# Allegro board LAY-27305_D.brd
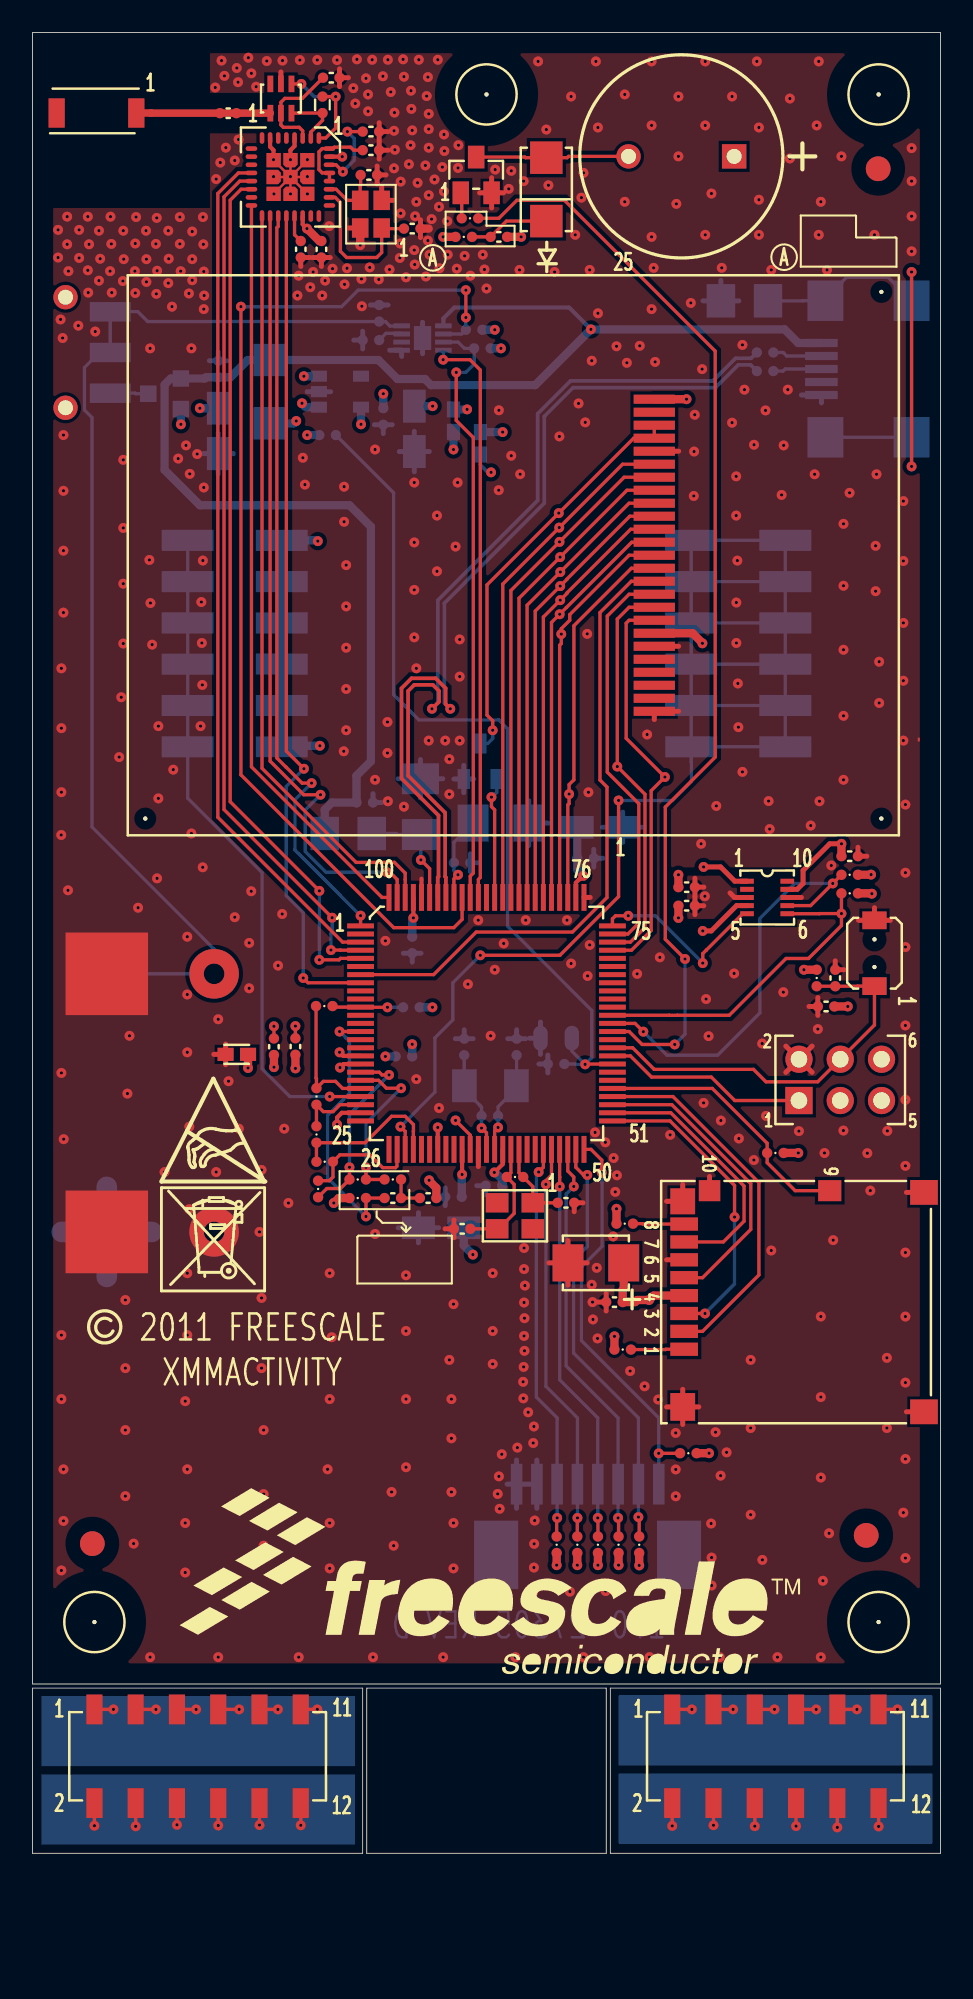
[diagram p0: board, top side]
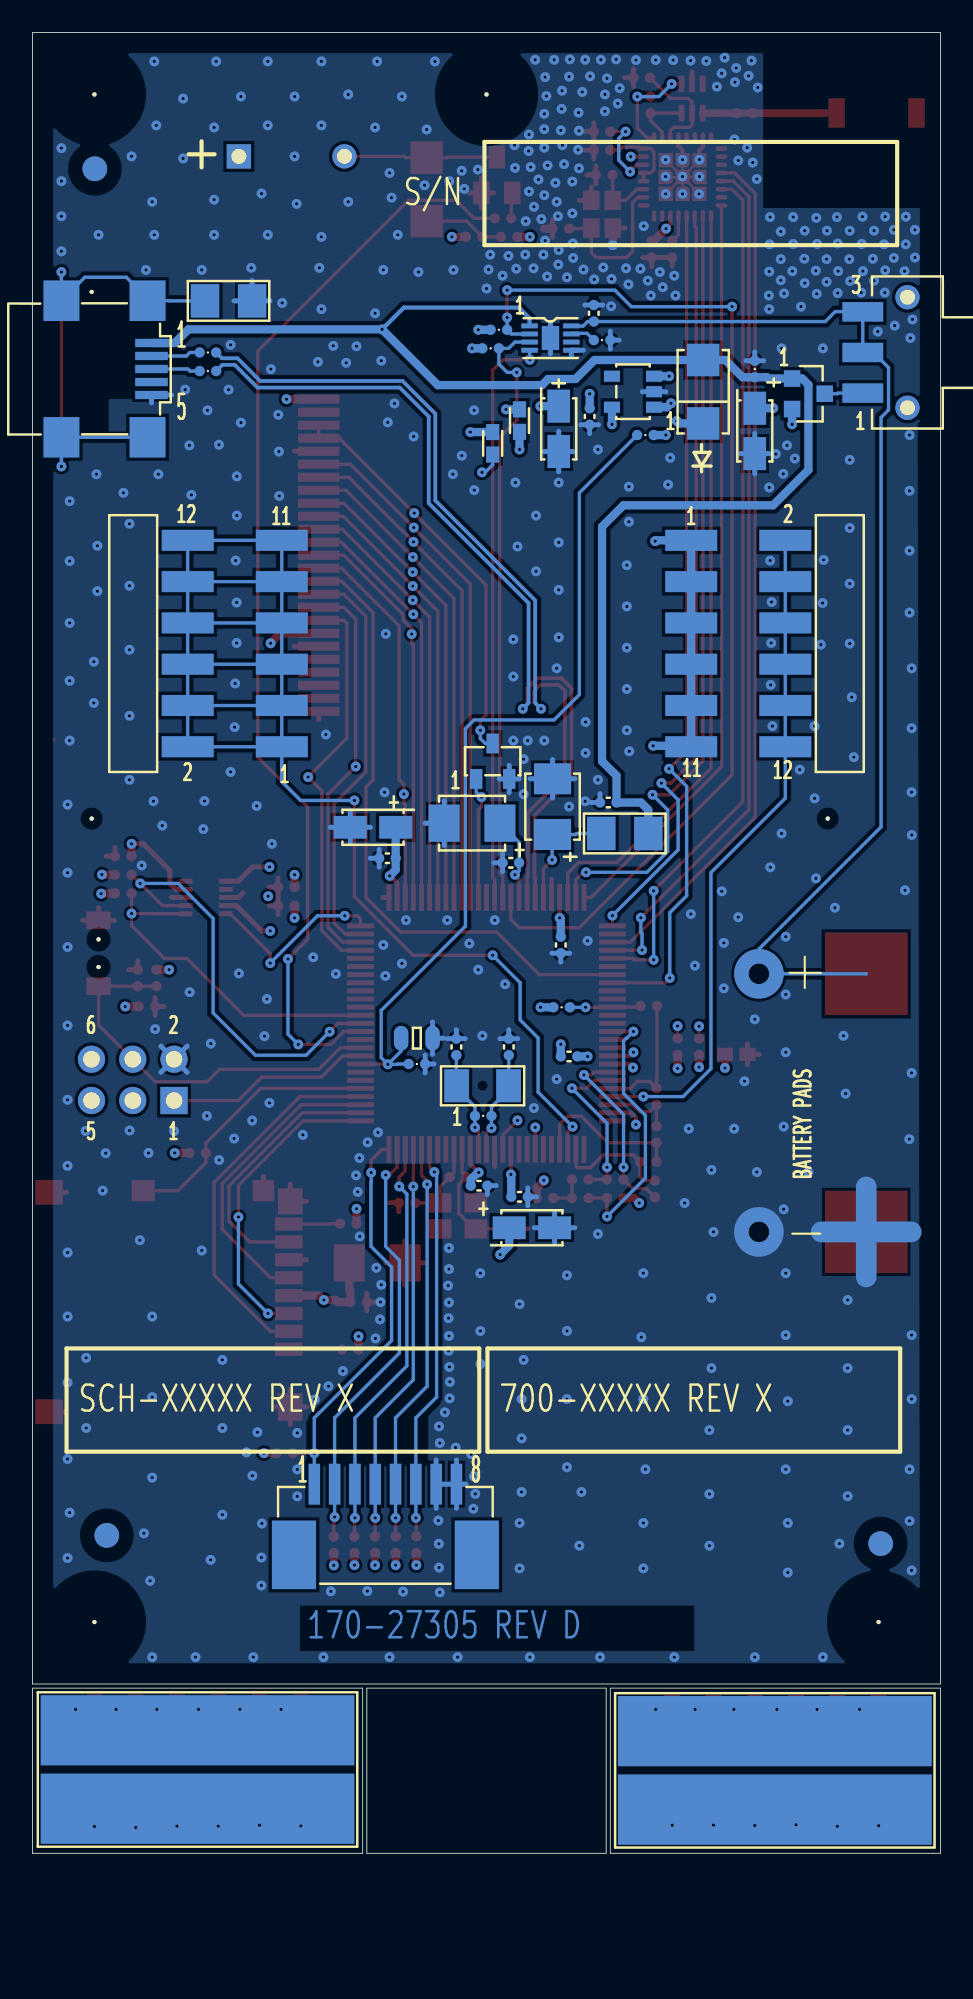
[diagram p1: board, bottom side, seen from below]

Outline 55.88 x 112.01 mm; copper layers: TOP, L2_GND_1, L3_PWR_1, L4_PWR_2, L5_GND_2, BOTTOM. Coordinates in mm from the lower left corner of the outline.
Outline path: 0,112.01 0,10.41 55.88,10.41 55.88,112.01 0,112.01 ; 0,10.16 20.32,10.16 20.32,0 0,0 0,10.16 ; 20.57,10.16 35.31,10.16 35.31,0 20.57,0 20.57,10.16 ; 35.56,10.16 55.88,10.16 55.88,0 35.56,0 35.56,10.16

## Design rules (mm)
net group DP1: nets USBDM USBDP
nets with their own width: min track width 0.305; nets VDDA

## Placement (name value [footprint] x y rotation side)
C1  0.47UF  [CC0402_25]  26.44 60.93 0 bottom
C2  4.7UF  [CC3528-21]  28.83 63.37 0 bottom
C3  4.7UF  [CC3528-21]  23.88 64.39 90 bottom
C4  1.0UF  [CC0402_25]  20.45 64.64 0 bottom
C5  2.2UF  [CC0402_25]  21.34 94.74 90 bottom
C6  10UF  [CC3216]  11.43 87.5 270 bottom
C7  0.1uF  [CC0402_25]  21.59 88.39 270 bottom
C8  10UF  [CC3216]  23.5 87.63 270 bottom
C9  0.1uF  [CC0402_25]  35.81 33.91 180 top
C10  4.7UF  [CC3528-21]  34.67 36.32 180 top
C11  0.1UF  [CC0402_25]  14.86 49.62 270 top
C12  0.01UF  [CC0402_25]  16.18 49.63 270 top
C13  10UF  [CC3216]  34.92 63.12 0 bottom
C14  0.1UF  [CC0402_25]  23.37 55.88 270 bottom
C15  0.1UF  [CC0402_25]  34.04 61.21 0 bottom
C16  0.1UF  [CC0402_25]  28.4 41.07 180 bottom
C17  10UF  [CC3216]  25.15 38.48 180 bottom
C20  0.1UF  [CC0402_25]  48.84 52.1 180 top
C21  0.1UF  [CC0402_25]  40.26 58.29 180 top
C22  0.1UF  [CC0402_25]  50.29 61.34 0 top
C23  0.1UF  [CC0402_25]  25.91 40.39 180 bottom
C24  0.1UF  [CC0402_25]  22.86 49.02 0 bottom
C25  0.1UF  [CC0402_25]  49.4 53.85 270 top
C28  12PF  [CC0402_25]  26.44 38.42 0 top
C29  12PF  [CC0402_25]  32.83 40.02 180 top
C30  0.1uF  [CC0402_25]  20.83 105.92 0 top
C31  0.1uF  [CC0402_25]  16.51 98.68 270 top
C32  0.1uF  [CC0402_25]  20.83 104.78 0 top
C33  1UF  [CC0402_25]  17.78 98.68 270 top
C34  10PF  [CC0402_25]  18.39 109.23 0 top
C35  10PF  [CC0402_25]  12.04 107.05 180 top
C36  6.8PF  [CC0402_25]  23.37 99.95 0 top
C37  6.8PF  [CC0402_25]  20.7 103.25 0 top
C38  0.1uF  [CC0402_25]  24.35 40.31 0 top
C39  0.1uF  [CC0402_25]  22.17 40.31 180 top
C40  0.01UF  [CC0402_25]  40.26 59.44 180 top
C41  0.01UF  [CC0402_25]  28.7 99.44 180 top
C42  18PF  [CC0402_25]  26.57 49.61 270 bottom
C43  18PF  [CC0402_25]  29.79 49.61 270 bottom
C45  0.1uF  [CC0805_OV]  32.23 50.14 180 bottom
CN1  Conn MicroSD  [CON_SDCARD_8F_SM_RA]  46.99 33.91 270 top
D1  FM4001  [DO214AC_AK]  14.61 89.92 90 bottom
D2  FM4001  [DO214AC_AK]  31.62 102.36 90 top
DS1  NHD-1.8-128160ZF-CTXL#  [LCDMODULE_25P_0P8_34X47_SMT]  29.59 79.86 90 top
E1  ANTENNA_2400MHZ  [ANTENNA-2450]  3.94 107.06 180 top
E3  ELECTRODE  [ELECTRODE2_REC_760X360]  10.2 5.1 180 bottom
E4  ELECTRODE  [ELECTRODE2_REC_760X360]  45.73 5.15 180 bottom
J1  USB-MiniB  [CON5_MUSB_B_SKT_RA_SM]  50.8 91.31 180 bottom
J3  08FFS-SP-TF  [CON_FFS_8F_50_SM_RA]  34.16 19.56 180 bottom
J8  CON SKT 12  [CON2X6_100_SM]  45.72 5.97 90 top
J9  CON PLUG 12  [CON2X6_100_RA_SM]  12.45 74.42 180 bottom
J10  CON PLUG 12  [CON2X6_100_RA_SM]  43.43 74.42 0 bottom
J11  CON SKT 12  [CON2X6_100_SM]  10.16 5.97 90 top
J12  HDR_2X3  [HDR203]  47.17 46.31 90 top
L1  26OHM  [IND_1206A]  43.81 95.5 180 bottom
L2  26OHM  [IND_1206A]  19.43 62.74 0 bottom
L3  100MHZ  [IND_0603]  12.57 49.15 180 top
L4  100MHZ  [IND_0603]  27.56 86.74 90 bottom
L5  100MHZ  [IND_0603]  25.91 88.14 90 bottom
L6  4.7nH  [IND_0402]  17.85 107.56 90 top
LS1  CSQG703BP  [BUZZER_6P5_12X3P8_TH]  43.18 104.39 180 top
NOREF  -  []  5.08 15.49 0 top
NOREF#2  -  []  35.56 0 0 top
NOREF#3  -  []  52.11 4.45 0 top
NOREF#4  -  []  3.17 13.59 0 top
NOREF#5  -  [unnamed#2]  52.07 108.2 0 top
NOREF#6  -  []  0 0 0 top
NOREF#7  -  []  55.88 10.41 90 top
NOREF#8  -  [unnamed#2]  51.31 19.56 0 top
NOREF#9  -  []  7.96 41.33 0 top
NOREF#10  -  []  222.76 -43.18 90 top
NOREF#11  -  []  372.36 -49.02 90 top
NOREF#12  -  []  201.42 112.9 0 top
NOREF#13  -  [unnamed#2]  3.68 19.05 0 top
NOREF#14  -  []  9.05 14.05 0 top
NOREF#15  -  []  243.08 -61.47 90 top
NOREF#16  -  []  -309.88 -248.03 0 top
NOREF#17  -  [unnamed#2]  52.04 103.63 0 top
NOREF#18  -  []  -285.75 277.75 0 top
NOREF#19  -  [unnamed#2]  52.07 14.22 0 top
NOREF#20  -  []  55.88 0 90 top
NOREF#21  -  []  0 112.01 0 top
NOREF#22  -  []  -23.98 -32.45 0 top
NOREF#23  -  [unnamed#2]  27.94 108.2 0 top
NOREF#24  -  []  4.57 32.51 0 top
NOREF#25  -  []  0 0 90 top
NOREF#26  -  [unnamed#2]  3.81 14.22 0 top
NOREF#27  -  []  5.08 15.49 0 top
NOREF#28  -  []  169.82 114.71 0 top
NOREF#29  -  []  55.88 10.16 0 top
NOREF#30  -  []  35.31 -0.25 0 top
NOREF#31  -  []  7.93 34.59 0 top
NOREF#32  -  []  3.56 4.57 0 top
NOREF#33  -  []  23.55 19.19 180 bottom
NOREF#34  -  []  53.59 29.59 180 bottom
NOREF#35  -  []  28.07 98.93 180 bottom
NOREF#36  -  [unnamed#2]  51.31 19.56 180 bottom
NOREF#37  -  [unnamed#2]  52.04 103.63 180 bottom
NOREF#38  -  [unnamed#2]  3.68 19.05 180 bottom
NOREF#39  -  []  27.69 29.59 180 bottom
Q1  ZXM61P02F  [SOT23-40X40]  8.13 89.79 270 bottom
Q3  MMBT5179  [SOT-23]  27.3 103.25 0 top
Q4  BSH103  [SOT23]  27.56 67.18 180 bottom
R3  33  [RC0402_25]  45.09 92.33 180 bottom
R4  33  [RC0402_25]  45.09 91.19 180 bottom
R5  4.7K  [RC0402_25]  27.18 93.73 180 bottom
R6  4.7K  [RC0402_25]  27.69 92.58 180 bottom
R8  1K  [RC0402_25]  11.43 91.31 90 bottom
R9  4.7K  [RC0402_25]  50.29 60.2 180 top
R10  10K  [RC0402_25]  36.32 30.99 0 top
R11  10K  [RC0402_25]  36.45 38.73 0 top
R12  10K  [RC0402_25]  45.72 43.08 180 top
R13  4.7K  [RC0402_25]  50.29 59.05 180 top
R15  1M  [RC0402_25]  29.69 41.61 0 top
R17  4.7K  [RC0402_25]  48.26 53.85 270 top
R18  1M  [RC0402_25]  32.22 48.56 180 bottom
R19  1M  [RC0402_25]  18.16 87.25 0 bottom
R20  1M  [RC0402_25]  17.48 44.22 90 top
R21  10K  [RC0402_25]  17.98 42.55 0 top
R22  10K  [RC0402_25]  17.48 46.56 90 top
R27  100K  [RC0402_25]  20.02 41.45 0 top
R28  100K  [RC0402_25]  23.32 52.04 0 bottom
R34  3.3K  [RC0402_25]  17.58 40.87 270 top
R35  3.3K  [RC0402_25]  17.96 52.12 0 top
R36  33K  [RC0402_25]  22.17 41.45 0 top
R38  1M  [RC0402_25]  20.02 40.31 180 top
R39  10K  [RC0402_25]  20.83 93.09 180 bottom
R40  470  [RC0402_25]  26.92 100.58 180 top
R41  0  [RC0402_25]  26.54 99.44 0 top
R42  1M  [RC0402_25]  28.14 45.36 0 bottom
R43  1M  [RC0402_25]  34.8 18.98 90 top
R44  1M  [RC0402_25]  33.53 18.98 90 top
R45  1M  [RC0402_25]  32.26 18.98 90 top
R46  1M  [RC0402_25]  36.07 18.98 90 top
R47  1M  [RC0402_25]  37.34 18.98 90 top
R48  1M  [RC0402_25]  40.36 24.61 180 top
SW1  JS102011SAQN  [SW3_SPDT_RA_SM]  2.03 92.33 0 bottom
SW2  SW2_STM151XX  [SW2_4X3MM_SM]  51.82 55.37 90 top
TP29  -  [TPAD_030]  4.57 38.23 0 top
TP30  -  [TPAD_030]  4.57 54.1 0 top
U1  MCF51MM256  [LQFP100_0P5_14X14]  27.94 51.05 0 top
U2  MC34673AEP  [DFN_8_0P5_2X3]  24 93.22 180 bottom
U3  LP2981IM5X3.3/NOPB  [SOT-23-5]  18.92 89.92 90 bottom
U5  MC13202FC  [QFN32_MC1320X]  15.88 103.12 270 top
U6  MMA7660FC  [DFN_10_0P5_3X3A]  45.21 58.8 0 top
Y1  16 MHz  [XTLOSC4_2P6X2P1MM_SM]  20.83 100.84 90 top
Y3  16MHZ  [XTLOSC4_3P2X2P5MM_SM]  29.69 39.22 180 top
Y4  32.768KHz  [XTL2_4P2X1P6]  28.18 47.22 180 bottom
Z1  50/200 OHMS  [XFMR6_0P65_2X1]  15.29 107.95 0 top

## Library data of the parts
C1 C4 C5 C7 C9 C11 C12 C14-C16 C20-C25 C28-C43 C45 = CAP_NP
C2 C3 C6 C8 C10 C13 C17 = CAP_POL
CN1 = CONN_MICRO_SD_CARD_REVERSED
D1 D2 = 3A_20V_SS32
DS1 = LCDMODULE_NHD_25P
E1 = ANTENNA_2P4GHZ
E3 E4 = ELECTRODE_B
J1 = USB_MINI_B_SKT
J3 = HDR_1X8_M
J8-J11 = CONN_HDR_6X2
J12 = CONN_HDR_3X2
L1 L2 = BEAD
L3-L5 = IND
L6 = INDUCTOR
LS1 = SPEAKER
Q1 = MOSFET_P
Q3 = NPN
Q4 = MOSFET_N
R3-R6 R8-R13 R15 R17-R22 R27 R28 R34-R36 R38-R48 = RES
SW1 = SW3_SPDT_SLIDE
SW2 = SW2_STM151XX
TP29 TP30 = TestLoop
U1 = MCF51MM256
U2 = MC34673AEP
U3 = LP2980_M5
U5 = MC13202FC
U6 = MMA7660FC
Y1 Y3 = XTAL_0
Y4 = XTAL
Z1 = LDB_21

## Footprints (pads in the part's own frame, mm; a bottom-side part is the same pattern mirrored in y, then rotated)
ANTENNA-2450
  rect 1.001x1.801 smd: 1(-2.451,0) 2(2.451,0)
BUZZER_6P5_12X3P8_TH
  rect 1.499x1.499 hole 0.914: 1(0,0)
  round 1.499 hole 0.914: 2(6.5,0)
CC0402_25
  round 0.635 smd: 1(-0.508,0) 2(0.508,0)
CC0805_OV
  oval 0.889x1.524 smd: 1(-0.965,0) 2(0.965,0)
CC3216
  rect 2.032x1.397 smd: 1(-1.397,0) 2(1.397,0)
CC3528-21
  rect 1.905x2.286 smd: 1(-1.714,0) 2(1.714,0)
CON2X6_100_RA_SM
  rect 3.2x1.295 smd: 1(-2.896,6.35) 2(2.896,6.35) 3(-2.896,3.81) 4(2.896,3.81) 5(-2.896,1.27) 6(2.896,1.27) 7(-2.896,-1.27) 8(2.896,-1.27) 9(-2.896,-3.81) 10(2.896,-3.81) 11(-2.896,-6.35) 12(2.896,-6.35)
CON2X6_100_SM
  round 0 hole 1.016 unplated: (-1.27,6.35) (-1.27,3.81) (-1.27,1.27) (-1.27,-1.27) (-1.27,-3.81) (-1.27,-6.35) (1.27,6.35) (1.27,3.81) (1.27,1.27) (1.27,-1.27) (1.27,-3.81) (1.27,-6.35)
  rect 1.829x0.991 smd: 1(2.883,6.35) 2(-2.883,6.35) 3(2.883,3.81) 4(-2.883,3.81) 5(2.883,1.27) 6(-2.883,1.27) 7(2.883,-1.27) 8(-2.883,-1.27) 9(2.883,-3.81) 10(-2.883,-3.81) 11(2.883,-6.35) 12(-2.883,-6.35)
CON5_MUSB_B_SKT_RA_SM
  rect 2.007x0.508 smd: 1(2.245,1.6) 2(2.245,0.8) 3(2.245,0) 4(2.245,-0.8) 5(2.245,-1.6)
  rect 2.21x2.489 smd: S1(1.999,4.201) S2(1.999,-4.201) S3(-3.299,4.201) S4(-3.299,-4.201)
CON_FFS_8F_50_SM_RA
  rect 2.718x4.216 smd: (-5.626,-1.199) (5.626,-1.199)
  rect 0.711x2.515 smd: 1(-4.374,3.15) 2(-3.124,3.15) 3(-1.875,3.15) 4(-0.625,3.15) 5(0.625,3.15) 6(1.875,3.15) 7(3.124,3.15) 8(4.374,3.15)
CON_SDCARD_8F_SM_RA
  rect 0.813x1.702 smd: 1(2.901,-6.886) 2(1.801,-6.886) 3(0.701,-6.886) 4(-0.399,-6.886) 5(-1.501,-6.886) 6(-2.601,-6.886) 7(-3.701,-6.886) 8(-4.801,-6.886)
  rect 1.295x1.422 smd: 9(-6.855,2.075)
  rect 1.295x1.321 smd: 10(-6.855,-5.324)
  rect 1.6x1.524 smd: 11(-6.2,-6.975)
  rect 1.524x1.702 smd: 12(-6.749,7.874) 13(6.749,7.874)
  rect 1.702x1.524 smd: 14(6.449,-6.975)
DFN_8_0P5_2X3
  rect 1.016x0.305 smd: 1(-1.285,0.749) 2(-1.285,0.249) 3(-1.285,-0.249) 4(-1.285,-0.749) 5(1.285,-0.749) 6(1.285,-0.249) 7(1.285,0.249) 8(1.285,0.749)
  rect 1.067x1.473 smd: 9(0,0)
DFN_10_0P5_3X3A
  rect 0.838x0.305 smd: 1(-1.239,1) 2(-1.239,0.5) 3(-1.239,0) 4(-1.239,-0.5) 5(-1.239,-1) 6(1.239,-1) 7(1.239,-0.5) 8(1.239,0) 9(1.239,0.5) 10(1.239,1)
DO214AC_AK
  rect 1.999x1.999 smd: 1(-1.951,0) 2(1.951,0)
ELECTRODE2_REC_760X360
  rect 19.304x4.318 smd: 1(0,2.413) 2(0,-2.413)
HDR203
  rect 1.676x1.676 hole 1.016: 1(0,0)
  round 1.676 hole 1.016: 2(2.54,0) 3(0,-2.54) 4(2.54,-2.54) 5(0,-5.08) 6(2.54,-5.08)
IND_0402
  round 0.635 smd: 1(-0.508,0) 2(0.508,0)
IND_0603
  rect 0.991x0.813 smd: 1(-0.691,0) 2(0.691,0)
IND_1206A
  rect 1.753x2.057 smd: 1(-1.448,0) 2(1.448,0)
LCDMODULE_25P_0P8_34X47_SMT
  round 0.254 hole 0.991 unplated: (-16.2,22.65) (-16.2,-22.65) (16.2,-22.65)
  rect 0.559x2.54 smd: 1(-9.6,-8.675) 2(-8.8,-8.675) 3(-8,-8.675) 4(-7.2,-8.675) 5(-6.4,-8.675) 6(-5.6,-8.675) 7(-4.8,-8.675) 8(-4,-8.675) 9(-3.2,-8.675) 10(-2.4,-8.675) 11(-1.6,-8.675) 12(-0.8,-8.675) 13(0,-8.675) 14(0.8,-8.675) 15(1.6,-8.675) 16(2.4,-8.675) 17(3.2,-8.675) 18(4,-8.675) 19(4.8,-8.675) 20(5.6,-8.675) 21(6.4,-8.675) 22(7.2,-8.675) 23(8,-8.675) 24(8.8,-8.675) 25(9.6,-8.675)
LQFP100_0P5_14X14
  rect 1.651x0.305 smd: 1(-7.75,5.999) 2(-7.75,5.499) 3(-7.75,5.001) 4(-7.75,4.501) 5(-7.75,4) 6(-7.75,3.5) 7(-7.75,3) 8(-7.75,2.499) 9(-7.75,1.999) 10(-7.75,1.501) 11(-7.75,1.001) 12(-7.75,0.5) 13(-7.75,0) 14(-7.75,-0.5) 15(-7.75,-1.001) 16(-7.75,-1.501) 17(-7.75,-1.999) 18(-7.75,-2.499) 19(-7.75,-3) 20(-7.75,-3.5) 21(-7.75,-4) 22(-7.75,-4.501) 23(-7.75,-5.001) 24(-7.75,-5.499) 25(-7.75,-5.999) 51(7.75,-5.999) 52(7.75,-5.499) 53(7.75,-5.001) 54(7.75,-4.501) 55(7.75,-4) 56(7.75,-3.5) 57(7.75,-3) 58(7.75,-2.499) 59(7.75,-1.999) 60(7.75,-1.501) 61(7.75,-1.001) 62(7.75,-0.5) 63(7.75,0) 64(7.75,0.5) 65(7.75,1.001) 66(7.75,1.501) 67(7.75,1.999) 68(7.75,2.499) 69(7.75,3) 70(7.75,3.5) 71(7.75,4) 72(7.75,4.501) 73(7.75,5.001) 74(7.75,5.499) 75(7.75,5.999)
  rect 0.305x1.651 smd: 26(-5.999,-7.75) 27(-5.499,-7.75) 28(-5.001,-7.75) 29(-4.501,-7.75) 30(-4,-7.75) 31(-3.5,-7.75) 32(-3,-7.75) 33(-2.499,-7.75) 34(-1.999,-7.75) 35(-1.501,-7.75) 36(-1.001,-7.75) 37(-0.5,-7.75) 38(0,-7.75) 39(0.5,-7.75) 40(1.001,-7.75) 41(1.501,-7.75) 42(1.999,-7.75) 43(2.499,-7.75) 44(3,-7.75) 45(3.5,-7.75) 46(4,-7.75) 47(4.501,-7.75) 48(5.001,-7.75) 49(5.499,-7.75) 50(5.999,-7.75) 76(5.999,7.75) 77(5.499,7.75) 78(5.001,7.75) 79(4.501,7.75) 80(4,7.75) 81(3.5,7.75) 82(3,7.75) 83(2.499,7.75) 84(1.999,7.75) 85(1.501,7.75) 86(1.001,7.75) 87(0.5,7.75) 88(0,7.75) 89(-0.5,7.75) 90(-1.001,7.75) 91(-1.501,7.75) 92(-1.999,7.75) 93(-2.499,7.75) 94(-3,7.75) 95(-3.5,7.75) 96(-4,7.75) 97(-4.501,7.75) 98(-5.001,7.75) 99(-5.499,7.75) 100(-5.999,7.75)
QFN32_MC1320X
  oval 0.711x0.279 smd: 1(-2.4,1.75) 2(-2.4,1.252) 3(-2.4,0.752) 4(-2.4,0.251) 5(-2.4,-0.251) 6(-2.4,-0.752) 7(-2.4,-1.252) 8(-2.4,-1.75) 17(2.4,-1.75) 18(2.4,-1.252) 19(2.4,-0.752) 20(2.4,-0.251) 21(2.4,0.251) 22(2.4,0.752) 23(2.4,1.252) 24(2.4,1.75)
  oval 0.279x0.711 smd: 9(-1.75,-2.4) 10(-1.252,-2.4) 11(-0.752,-2.4) 12(-0.251,-2.4) 13(0.251,-2.4) 14(0.752,-2.4) 15(1.252,-2.4) 16(1.75,-2.4) 25(1.75,2.4) 26(1.252,2.4) 27(0.752,2.4) 28(0.251,2.4) 29(-0.251,2.4) 30(-0.752,2.4) 31(-1.252,2.4) 32(-1.75,2.4)
  custom 0.738x0.738 smd: 33(0,0)
RC0402_25
  round 0.635 smd: 1(-0.508,0) 2(0.508,0)
SOT23
  rect 0.762x1.219 smd: 1(-1.016,-1.092) 2(1.016,-1.092) 3(0,1.092)
SOT23-40X40
  rect 1.016x1.016 smd: 1(-0.94,-1.003) 2(0.94,-1.003) 3(0,1.003)
SOT-23
  rect 1.016x1.397 smd: 1(-0.95,-1.1) 2(0.95,-1.1) 3(0,1.1)
SOT-23-5
  rect 0.686x0.991 smd: 1(-0.953,-1.295) 2(0,-1.295) 3(0.953,-1.295) 4(0.953,1.295) 5(-0.953,1.295)
SW2_4X3MM_SM
  round 0.254 hole 0.711 unplated: (-0.851,0) (0.851,0)
  rect 1.092x1.499 smd: 1(-2.024,0) 2(2.024,0)
SW3_SPDT_RA_SM
  round 1.499 hole 0.914: (0,-3.401) (0,3.401)
  rect 2.515x1.194 smd: 1(2.751,2.499) 2(2.751,0) 3(2.751,-2.499)
TPAD_030
  rect 5.08x5.08 smd: 1(0,0)
unnamed#2
  round 0.254 hole 3.175 unplated: (0,0)
XFMR6_0P65_2X1
  rect 0.356x1.016 smd: 1(-0.65,-0.899) 2(0,-0.899) 3(0.65,-0.899) 4(0.65,0.899) 5(0,0.899) 6(-0.65,0.899)
XTL2_4P2X1P6
  rect 1.524x2.032 smd: 1(-1.6,0) 2(1.6,0)
XTLOSC4_2P6X2P1MM_SM
  rect 1.194x1.016 smd: 1(-0.851,-0.66) 2(0.851,-0.66) 3(0.851,0.66) 4(-0.851,0.66)
XTLOSC4_3P2X2P5MM_SM
  rect 1.397x1.194 smd: 1(-1.1,-0.8) 2(1.1,-0.8) 3(1.1,0.8) 4(-1.1,0.8)

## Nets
3.3V: C7.1 C8.1 C9.1 C10.1 C20.1 C22.1 C33.1 C41.1 CN1.4(VDD) DS1.7(VDD) DS1.25(LED+) J12.6(B3) L5.2 LS1.1 R5.1 R6.1 R9.1 R10.1 R11.1 R12.1 R13.1 R41.1 R43.1 R44.1 R45.1 R46.1 R47.1 R48.1 U3.5(VOUT) U5.22(VDDINT) U5.31(VBATT) U6.9(DVDD)
GND: C1.2 C2.2 C3.2 C4.2 C5.2 C6.2 C7.2 C8.2 C9.2 C10.2 C13.2 C14.2 C15.2 C16.2 C17.2 C20.2 C22.2 C23.2 C25.1 C28.1 C29.1 C30.2 C31.2 C32.2 C33.2 C34.2 C36.2 C37.2 C42.1 C43.1 C45.2 CN1.6(VSS1) CN1.10(CD_COMMON) CN1.11(VSS2) CN1.12(VSS3) CN1.13(VSS4) CN1.14(VSS5) DS1.1(GND1) DS1.6(GND2) DS1.21(GND3) J1.5(GND1) J3.7 J3.8 J12.2(B1) L1.2 L3.2 Q3.2(EMITTER) Q4.2(SOURCE) R8.2 R18.2 R39.2 SW2.2(SW2) TP29.1(PIN1) U1.37(VSS2) U1.76(VSS3) U1.96(VSS1) U2.5(GND) U2.9(EPAD) U3.2(GND) U5.4(NC) U5.7(SM) U5.33(EP) U6.8(DVSS) Y1.2 Y1.4 Z1.5(CT)
GND_FIELD SIGNAL: C11.2 C12.2 C21.2 C24.1 C40.2 L3.1 U1.17(VSSA) U1.18(VREFL) U6.1(RESERVED) U6.4(AVSS)
VBATT: C6.1 D1.1(CATHODE) Q1.2(SOURCE) R19.1 U3.1(VIN) U3.3(ON/O\F\F\)
VBUS: C4.1 D1.2(ANODE) J1.1(VBUS) L2.1 Q1.1(GATE) R8.1 U2.1(VIN)
VDDA: C11.1 C12.1 C21.1 C40.1 L4.1 U1.36(VDDA) U6.3(AVDD)
VINN1: R20.2 R22.1 U1.23(VINN1/DADM2)
VINN2: R20.1 R21.1 U1.29(VINN2/DADM3)
VINP1: J9.2(B1) J9.4(B2) J9.6(B3) J9.8(B4) J9.10(B5) J9.12(B6) U1.22(VINP1)
VINP2: J10.1(A1) J10.2(B1) J10.3(A2) J10.4(B2) J10.5(A3) J10.6(B3) J10.7(A4) J10.8(B4) J10.9(A5) J10.10(B5) J10.11(A6) J10.12(B6) U1.28(VINP2)
ACC_INT: U1.75(PTE4/CMPP3/TPMCLK/IRQ) U6.5(I\N\T\)
ACC_SCL: R13.2 U1.64(PTD5/SCL/RGPIOP11/TPM1CH3) U6.6(SCL)
ACC_SDA: R9.2 U1.63(PTD4/SDA/RGPIOP10/TPM1CH2) U6.7(SDA)
BK_LIGHT: Q4.1(GATE) U1.87(PTJ7/FB_AD13)
BKGD: J12.1(A1) U1.59(PTD0/BKGD/MS)
BUZZER: R40.1 U1.62(PTD3/USB_PULLUPP(D+)/RGPIOP9/TP)
EXTAL1: C42.2 R42.1 U1.38(PTB2/EXTAL1) Y4.2
EXTAL2: C28.2 R15.1 U1.41(PTB4/EXTAL2) Y3.3
INP1+: R28.1 R35.2 U1.11(PTA4/INP1+)
INP1-: R27.1 R34.2 U1.19(INP1-)
INP2+: C39.2 R38.1 U1.14(PTA7/INP2+)
LCD_CS: DS1.8(CS) U1.72(PTE1/KBI2P4/RGPIOP13/FB_AD6)
LCD_D0: DS1.12(DO) U1.78(PTE5/FB_D7/USB_SESSVLD/TX2)
LCD_D1: DS1.13(D1) U1.79(PTE6/FB_RW_B/USB_SESSEND/RX2)
LCD_D2: DS1.14(D2) U1.80(PTE7/USB_VBUSVLD/TPM2CH3)
LCD_D3: DS1.15(D3) U1.81(PTF0/USB_ID/TPM2CH2)
LCD_D4: DS1.16(D4) U1.82(PTF1/RX2/USB_DP_DOWN/TPM2CH1)
LCD_D5: DS1.17(D5) U1.83(PTF2/TX2/USB_DM_DOWN/TPM2CH0)
LCD_D6: DS1.18(D6) U1.84(PTJ4/RGPIOP15/FB_AD16)
LCD_D7: DS1.19(D7) U1.85(PTJ5/FB_AD15)
LCD_RD: DS1.11(RD) U1.7(PTH1/FB_D0)
LCD_RS: DS1.9(RS) U1.73(PTE2/KBI2P5/RGPIOP14/FB_AD7)
LCD_RST: DS1.20(RST) U1.86(PTJ6/FB_AD14)
LCD_WR: DS1.10(WR) U1.74(PTE3/KBI2P6/FB_AD8)
MCU3.3V: C13.1 C14.1 C15.1 C16.1 C17.1 C23.1 L4.2 L5.1 R17.1 U1.35(VREFH) U1.40(VDD2) U1.77(VDD3) U1.97(VDD1)
MCU_RESET: C25.2 J12.4(B2) R17.2 SW2.1(SW1) U1.60(PTD1/CMPP2/RESET)
OUT1: R27.2 R36.1 U1.20(OUT1)
PTG0: R6.2 U1.90(PTF4/SDA/FB_D4/FB_AD10) U2.3(C\H\G\)
PTG1: R5.2 U1.91(PTF5/KBI2P7/FB_D3/FB_AD9) U2.2(P\P\R\)
PTG2: U1.89(PTF3/SCL/FB_D5/FB_AD11) U2.4(E\N\)
SD_CS: CN1.2(CD/DAT3) U1.54(PTC3/KBI1P6/SS2/ADP7)
SD_INT: CN1.9(CD_SW) R12.2 U1.55(PTC4/KBI1P7/CMPP0/ADP8)
SD_MISO: CN1.7(DAT0) U1.52(PTC1/MISO2/FB_D0/FB_AD1)
SD_MOSI: CN1.3(CMD) U1.51(PTC0/MOSI2/FB_OE_B/FB_CS0)
SD_SCLK: CN1.5(CLK) U1.53(PTC2/KBI1P5/SPSCK2/ADP6)
T_CNTR: J3.2 R47.2 U1.49(PTH6/RGPIOP6/FB_D3)
T_DWN: J3.6 R45.2 U1.45(PTH2/RGPIOP2/FB_D7)
T_LEFT: J3.5 R44.2 U1.46(PTH3/RGPIOP3/FB_D6)
T_REF: J3.4 R43.2 U1.47(PTH4/RGPIOP4/FB_D5)
T_RIGHT: J3.1 R48.2 U1.50(PTH7/RGPIOP7/FB_D2)
T_TOP: J3.3 R46.2 U1.48(PTH5/RGPIOP5/FB_D4)
TRIOUT1: R22.2 R35.1 U1.21(TRIOUT1/DADP2)
TRIOUT2: R21.2 R34.1 U1.27(TRIOUT2/DADP3)
USBDM: R3.2 U1.93(USB_DM)
USBDP: R4.2 U1.94(USB_DP)
VREF1.6V: C24.2 C38.2 J9.1(A1) J9.3(A2) J9.5(A3) J9.7(A4) J9.9(A5) J9.11(A6) R28.2 R38.2 U1.24(INP2-) U1.32(VREFO)
XTAL1: C43.2 R42.2 U1.39(PTB3/XTAL1) Y4.1
XTAL2: C29.2 R15.2 U1.42(PTB5/XTAL2) Y3.1
ZIG_ATTN: U1.5(PTG7/FB_AD18) U5.14(/ATTN)
ZIG_CS: U1.1(PTA0/FB_D2/SS1) U5.19(/CE)
ZIG_INT: U1.8(PTA1/KBI1P0/TX1/FB_D1) U5.20(/IRQ)
ZIG_MISO: U1.99(PTF7/MISO1) U5.18(MISO)
ZIG_MOSI: U1.98(PTF6/MOSI1) U5.17(MOSI)
ZIG_MRST: U1.3(PTG5/FB_RW_B) U5.12(/RST)
ZIG_RXTXEN: U1.4(PTG6/FB_AD19) U5.13(RXTXEN)
ZIG_SPCLK: U1.100(PTG0/SPSCK1) U5.16(SPICLK)
N01665: Q1.3(DRAIN) SW1.1(NC)
N02698: J1.S1(SHLD1) J1.S2(SHLD2) J1.S3(SHLD3) J1.S4(SHLD4) L1.1
N02810: J1.2(D-) R3.1
N02910: C1.1 C2.1 U1.92(VUSB33)
N03154: C5.1 SW1.2(COM) SW1.3(NO) TP30.1(PIN1) U2.8(BAT)
N03295: R39.1 U2.7(ISET)
N04574: CN1.1(DAT2) R10.2
N04614: CN1.8(DAT1) R11.2
N25309: C45.1 R18.1 R19.2 U1.58(PTC7/KBI2P2/CLKOUT/ADP11)
N32500: C38.1 C39.1 R36.2
N41665: C30.1 U5.30(VDDVCO)
N41677: C31.1 U5.21(VDDD)
N41695: C32.1 U5.28(VDDLO2) U5.29(VDDLO1) U5.32(VDDA)
N42211: L6.1 U5.2(RIN_P) Z1.3(BAL3)
N42218: L6.2 U5.1(RIN_M) Z1.4(BAL4)
N42330: C34.1 U5.3(CT_BIAS) Z1.2(UNBAL2)
N42476: C35.1 C35.2 E1.1 Z1.1(UNBAL1)
N42716: C36.1 U5.26(XTAL1) Y1.1
N42769: C37.1 U5.27(XTAL2) Y1.3
N99672: J1.3(D+) R4.1
N131191: Q3.1(BASE) R40.2
N131207: D2.2(ANODE) LS1.2 Q3.3(COLLECTOR)
N131223: C41.2 D2.1(CATHODE) R41.2
N132740: DS1.22(LED1-) DS1.23(LED2-) Q4.3(DRAIN)
N151371: C3.1 L2.2 U1.95(VBUS)
N217381: E4.1 J8.1(A1) J8.3(A2) J8.5(A3) J8.7(A4) J8.9(A5) J8.11(A6)
N217421: E4.2 J8.2(B1) J8.4(B2) J8.6(B3) J8.8(B4) J8.10(B5) J8.12(B6)
N217461: E3.1 J11.1(A1) J11.3(A2) J11.5(A3) J11.7(A4) J11.9(A5) J11.11(A6)
N217497: E3.2 J11.2(B1) J11.4(B2) J11.6(B3) J11.8(B4) J11.10(B5) J11.12(B6)

Pads without a net: DS1 2 3 4 5 24; E1 2; J1 4; J12 3 5; U1 2 6 9 10 12 13 15 16 25 26 30 31 33 34 43 44 56 57 61 65 66 67 68 69 70 71 88; U2 6; U3 4; U5 5 6 8 9 10 11 15 23 24 25; U6 2 10; Y3 2 4; Z1 6

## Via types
v1: diameter 0.61, hole 0.203, TOP to BOTTOM, 683 vias
v2: diameter 3.048, hole 1.27, TOP to BOTTOM, 2 vias

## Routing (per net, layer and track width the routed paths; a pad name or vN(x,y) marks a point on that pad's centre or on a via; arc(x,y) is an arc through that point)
3.3V: length 45.5
  TOP w0.254: U5.31 v1(19.06,104.38) ; v1(16.89,99.95) 16.63,100.21 U5.22
  TOP w0.305: v1(49.78,62.1) 49.06,62.1 47.42,60.46 47.42,59.66 47.06,59.3 U6.9
  TOP w0.508: DS1.25 v1(40.25,89.45) ; R46.1 v1(36.07,17.72) ; R12.1 v1(47.13,43.08) ; R13.1 51.59,59.05 51.61,59.03 v1(51.65,59.03) ; R48.1 v1(41.64,24.61) ; R9.1 51.54,60.2 51.55,60.21 v1(51.61,60.21) ; R43.1 v1(34.8,17.72) ; v1(16.89,99.95) 17.65,99.19 C33.1 ; C22.1 v1(49.78,62.1) ; C20.1 v1(50.18,52.1) ; C10.1 36.39,34.72 36.32,34.66 C9.1 37.08,33.91 37.21,34.04 v1(37.95,34.04) 38.22,34.31 CN1.4 ; R44.1 v1(33.53,17.72) ; C41.1 v1(30.07,99.44) ; R10.1 v1(35.81,31.8) ; R45.1 v1(32.26,17.72) ; R47.1 v1(37.34,17.71) ; R11.1 v1(35.94,39.65) ; DS1.7 40.63,75.05 41.23,74.46 v1(41.23,74.44) ; R41.1 v1(25.27,99.44)
  L4_PWR_2 w0.508: 51.44,49.65 J12.6 ; J12.6 51.44,48.04 ; J12.6 53.06,49.65 ; J12.6 53.06,48.04 ; 42.44,103.65 LS1.1 ; LS1.1 43.92,103.65 ; LS1.1 43.92,105.14 ; LS1.1 42.44,105.14
  BOTTOM w0.508: L5.2 v1(26.75,88.83) ; R5.1 v1(28.45,93.73) ; C8.1 v1(24.63,89.03) ; C7.1 v1(21.59,89.79) ; U3.5 v1(20.22,87.91) ; R6.1 v1(28.83,92.58)
GND: length 156.3
  TOP w0.254: U5.7 14.62,104.99 14.83,104.78 v1(14.83,104.19) ; U5.4 16.13,105.03 15.88,104.78 v1(15.88,104.19) ; U1.96 23.94,59.96
  TOP w0.305: 49.4,54.9 C25.1 49.95,54.36 ; 25.39,38.42 C28.1 ; C28.1 25.93,37.87 ; C28.1 25.93,38.96 ; 53.78,27.16 CN1.13 ; C20.2 48.33,52.64 ; C20.2 48.33,51.55 ; C20.2 47.78,52.1 ; 40.02,26.38 CN1.14 ; CN1.14 40.02,28.54 ; CN1.14 39.02,27.46 ; CN1.14 41.01,27.46 ; 50.8,61.89 C22.2 51.35,61.34 ; Q3.2 28.99,102.15 ; Q3.2 28.25,103.08 ; Q3.2 27.52,102.15 ; Q3.2 28.25,101.22 ; 21.34,105.37 C30.2 ; C30.2 21.88,105.92 ; C30.2 21.34,106.46 ; 38.27,69.75 DS1.1 39.77,70.26 ; 19.43,99.99 Y1.4 ; 46.36,49.65 J12.2 ; J12.2 47.98,48.04 ; J12.2 46.36,48.04 ; J12.2 47.98,49.65 ; C32.2 21.88,104.78 ; C32.2 21.34,105.32 ; C32.2 21.34,104.23 ; 11.16,49.15 L3.2 ; L3.2 11.88,49.78 ; L3.2 11.88,48.51 ; 16.51,97.62 C31.2 17.06,98.17 ; 34.76,33.91 C9.2 ; C9.2 35.31,34.46 ; C9.2 35.31,33.36 ; 17.23,98.17 C33.2 ; C33.2 18.33,98.17 ; C33.2 17.78,97.62 ; C34.2 19.44,109.23 ; C34.2 18.9,109.78 ; C34.2 18.9,108.69 ; 21.49,102.51 Y1.2 22.23,101.69 ; 23.88,100.5 C36.2 23.88,99.4 ; SW2.2 52.79,57.4 ; SW2.2 51.82,58.17 ; SW2.2 50.84,57.4 ; 33.88,40.02 C29.1 33.34,39.47 ; 53.78,40.66 CN1.12 ; 39.02,36.51 CN1.6 ; 39.02,40.11 CN1.11 40.02,41.14 ; DS1.21 39.77,86.26 ; 21.21,102.7 C37.2 ; C37.2 21.76,103.25 ; C37.2 21.21,103.8 ; 27.44,42.25 U1.37 ; 31.77,36.32 C10.2 ; C10.2 32.96,37.69 ; C10.2 34.14,36.32 ; C10.2 32.96,34.95 ; Z1.5 15.29,109.59 ; CN1.10 41.67,41.64 ; 47.32,58.8 U6.8 ; DS1.6 39.77,74.26 ; U1.76 34.32,58.8
  TOP w0.508: C36.2 24.38,99.95 ; Y1.4 v1(20.17,98.93)
  L2_GND_1 w0.508: J12.2 47.98,48.04 ; J12.2 46.36,49.65 ; J12.2 46.36,48.04 ; J12.2 47.98,49.65
  L5_GND_2 w0.508: 46.36,48.04 J12.2 ; J12.2 46.36,49.65 ; J12.2 47.98,49.65 ; J12.2 47.98,48.04
  BOTTOM w0.305: C42.1 26.57,50.66 ; C42.1 26.02,50.11 ; C42.1 27.12,50.11 ; 21.98,92.47 U2.5 22.72,92.09 ; 24,92.25 U2.9 24,94.18 ; C2.2 31.73,63.37 ; C2.2 30.54,64.75 ; C2.2 30.54,62 ; 29.2,22.71 J3.8 ; J3.8 30.37,22.71 ; J3.8 29.79,24.19 ; J3.8 29.79,21.22 ; 27.34,41.07 C16.2 27.89,40.53 ; 34.54,60.67 C15.2 ; C15.2 35.09,61.21 ; C15.2 34.54,61.76 ; C43.1 29.79,50.66 ; C43.1 30.34,50.11 ; C43.1 29.25,50.11 ; 16.9,89.92 U3.2 18.35,89.92 ; 23.75,38.48 23.75,39.41 ; 23.75,38.48 24.99,38.48 ; 23.75,38.48 22.5,38.48 ; 23.75,38.48 23.75,37.55 ; 23.37,54.83 C14.2 ; C14.2 23.91,55.37 ; C14.2 22.82,55.37 ; 25.4,39.84 C23.2 ; C23.2 24.85,40.39 ; C23.2 25.4,40.93 ; 20.95,65.19 C4.2 21.5,64.64 ; C6.2 11.43,87.35 ; C6.2 10.5,86.11 ; C6.2 12.36,86.11 ; C6.2 11.43,84.86 ; 22.5,66.1 C3.2 ; C3.2 23.88,67.29 ; C3.2 23.88,64.92 ; C3.2 25.25,66.1 ; 31.71,48.01 R18.2 ; R18.2 31.71,49.1 ; R18.2 31.17,48.56 ; 10.88,91.82 R8.2 ; R8.2 11.98,91.82 ; R8.2 11.43,92.37 ; C13.2 36.32,64.05 ; C13.2 35.08,63.12 ; C13.2 37.57,63.12 ; C13.2 36.32,62.19 ; 23.5,84.99 23.5,86.23 ; 23.5,86.23 22.57,86.23 ; 23.5,86.23 24.42,86.23 ; 23.5,86.23 23.5,87.48 ; 46.36,49.65 J12.2 ; J12.2 47.98,48.04 ; J12.2 46.36,48.04 ; J12.2 47.98,49.65 ; 26.54,65.25 Q4.2 ; Q4.2 26.54,66.93 ; Q4.2 27.15,66.09 ; Q4.2 25.93,66.09 ; 31.26,49.15 C45.2 ; C45.2 31.26,51.14 ; C45.2 30.59,50.14 ; 20.32,92.54 R39.2 ; R39.2 19.77,93.09 ; R39.2 20.32,93.64 ; 41.26,95.5 L1.2 ; L1.2 43.47,95.5 ; L1.2 42.37,96.76 ; 31.04,21.22 J3.7 ; J3.7 30.45,22.71 ; J3.7 31.04,24.19 ; C1.2 27.5,60.93 ; C1.2 26.95,60.39 ; C1.2 26.95,61.48 ; 48.55,89.23 J1.5 47.32,89.71 ; 20.79,95.25 C5.2 21.88,95.25 ; 21.04,87.88 C7.2 ; C7.2 22.14,87.88 ; C7.2 21.59,87.34
  BOTTOM w1.27: TP29.1 4.57,41 ; TP29.1 7.34,38.23 ; TP29.1 1.8,38.23 ; TP29.1 4.57,35.46
  vias: v1(1.57,99.87) v1(1.57,98.17) v1(1.73,94.36) v1(1.78,72.9) v1(1.78,69.22) v1(1.78,65.28) v1(1.77,62.64) v1(1.78,48.01) v1(1.78,31.88) v1(1.78,27.94) v1(1.78,17.4) v1(1.85,93.22) v1(1.91,87.25) v1(1.91,83.82) v1(1.91,80.14) v1(1.91,76.33) v1(1.92,43.93) v1(1.91,23.62) v1(1.91,20.45) v1(2.13,100.69) v1(2.13,98.98) v1(2.21,97.33) v1(2.18,59.24) v1(2.82,93.98) v1(2.87,99.87) v1(2.87,98.15) v1(3.4,100.69) v1(3.4,97.38) v1(3.43,96.01) v1(3.48,98.98) v1(3.86,93.62) v1(4.09,99.82) v1(4.09,96.75) v1(4.17,98.09) v1(4.8,100.69) v1(4.78,97.33) v1(4.85,99.01) v1(4.88,96.01) v1(5.33,67.44) v1(5.46,71.12) v1(5.59,99.82) v1(5.61,98.07) v1(5.56,96.72) v1(5.59,85.73) v1(5.59,81.53) v1(5.59,78.11) v1(5.59,74.42) v1(5.71,34.04) v1(5.71,29.84) v1(5.71,26.04) v1(5.71,21.97) v1(5.84,46.74) v1(5.97,50.29) v1(6.22,19.05) v1(6.32,99.03) v1(6.3,97.33) v1(6.32,95.99) v1(6.38,100.66) v1(6.5,58.17) v1(6.99,99.82) v1(7.01,98.07) v1(7.01,96.67) v1(7.24,92.58) v1(7.19,79.57) v1(7.24,12.06) v1(7.26,76.92) v1(7.36,74.36) v1(7.65,100.61) v1(7.59,99.01) v1(7.62,95.94) v1(7.67,97.36) v1(7.75,69.34) v1(7.75,64.9) v1(7.67,59.98) v1(8.13,41.91) v1(8.36,99.82) v1(8.38,98.09) v1(8.36,96.6) v1(8.59,95.15) v1(8.66,66.66) v1(8.97,85.8) v1(9.07,100.66) v1(9.07,99.01) v1(9.12,97.33) v1(9.45,86.61) v1(9.4,27.81) v1(9.4,20.32) v1(9.4,17.27) v1(9.53,56.39) v1(9.53,52.83) v1(9.53,49.28) v1(9.53,35.69) v1(9.53,31.88) v1(9.53,23.62) v1(9.63,95.96) v1(9.68,84.86) v1(9.65,44.7) v1(9.65,39.62) v1(9.83,99.77) v1(9.83,98.07) v1(9.83,96.77) v1(9.78,92.58) v1(9.78,62.74) v1(10.13,86.08) v1(10.34,69.34) v1(10.39,76.98) v1(10.42,74.46) v1(10.49,100.66) v1(10.52,98.98) v1(10.54,97.31) v1(10.54,95) v1(10.54,84.02) v1(10.49,79.53) v1(10.45,71.88) v1(10.47,60.66) v1(10.57,95.83) v1(11.25,108.63) v1(11.3,103) v1(11.3,41.91) v1(11.43,51.31) v1(11.43,12.06) v1(11.63,110.29) v1(11.56,104.01) v1(11.81,109.35) v1(11.9,104.93) v1(12.06,47.5) v1(12.45,104.14) v1(12.45,57.59) v1(12.57,109.83) v1(12.65,108.96) v1(12.68,105.43) v1(12.7,44.58) v1(13.28,110.46) v1(13.34,56.01) v1(13.34,53.21) v1(13.47,109.5) v1(13.46,59.18) v1(13.76,108.68) v1(13.97,38.23) v1(14.1,42.04) v1(14.1,34.16) v1(14.1,29.84) v1(14.22,26.04) v1(14.22,22.1) v1(14.22,18.92) v1(14.42,110.26) v1(14.83,103.15) v1(14.86,102.08) v1(15.11,54.61) v1(15.38,110.29) v1(15.37,57.79) v1(15.49,44.58) v1(15.75,40.01) v1(15.88,103.15) v1(15.88,102.08) v1(16.31,95.83) v1(16.38,97.05) v1(16.38,12.06) v1(16.45,110.32) v1(16.64,85.85) v1(16.76,84.2) v1(16.92,104.19) v1(16.92,103.15) v1(16.92,102.08) v1(17.09,96.34) v1(17.27,97.28) v1(17.53,110.32) v1(17.83,95.83) v1(18.01,96.75) v1(18.16,23.62) v1(18.26,100.1) v1(18.29,35.69) v1(18.29,27.94) v1(18.29,20.32) v1(18.29,17.53) v1(18.41,31.75) v1(18.47,97.49) v1(18.74,110.32) v1(19.2,96.52) v1(19.18,84.07) v1(19.18,81.92) v1(19.15,67.8) v1(19.3,79.25) v1(19.3,76.71) v1(19.3,74.17) v1(19.3,71.63) v1(19.3,69.09) v1(19.35,97.51) v1(19.75,108.59) v1(19.87,107.65) v1(19.96,110.36) v1(20.24,96.85) v1(20.27,95.17) v1(20.52,109.19) v1(20.65,108.2) v1(20.65,107.17) v1(20.75,97.56) v1(20.9,110.34) v1(20.95,12.06) v1(21.08,86.36) v1(21.08,66.04) v1(21.08,38.1) v1(21.31,96.82) v1(21.56,109.32) v1(21.72,56.13) v1(21.84,69.6) v1(21.84,67.69) v1(21.87,110.34) v1(21.87,64.72) v1(22.05,108.36) v1(21.97,97.43) v1(22.1,22.23) v1(22.23,18.92) v1(22.28,107.09) v1(22.25,105.97) v1(22.3,104.8) v1(22.25,103.66) v1(22.63,99.03) v1(22.61,98.15) v1(22.66,102.84) v1(22.66,100.89) v1(22.81,110.36) v1(22.86,109.3) v1(22.86,64.39) v1(22.99,96.95) v1(22.99,35.56) v1(22.99,32.13) v1(22.99,27.94) v1(22.99,23.75) v1(23.16,103.91) v1(23.29,108.43) v1(23.32,107.31) v1(23.27,105.08) v1(23.37,105.99) v1(23.55,100.71) v1(23.5,98.63) v1(23.52,97.74) v1(23.5,84.33) v1(23.5,80.64) v1(23.5,77.72) v1(23.5,74.8) v1(23.62,101.6) v1(23.62,72.9) v1(23.62,47.62) v1(23.7,102.77) v1(23.77,110.34) v1(24.18,103.84) v1(24.21,97) v1(24.33,109.27) v1(24.26,108.1) v1(24.33,99.21) v1(24.38,107.01) v1(24.38,106.07) v1(24.38,104.93) v1(24.38,102.01) v1(24.43,98.35) v1(24.38,68.45) v1(24.56,100.53) v1(24.74,102.97) v1(24.94,110.34) v1(24.89,82.3) v1(24.89,78.87) v1(25.02,101.3) v1(25.04,97.51) v1(25.02,45.85) v1(25.22,103.73) v1(25.32,105.74) v1(25.35,104.72) v1(25.32,102.23) v1(25.27,12.06) v1(25.4,68.45) v1(25.53,100.41) v1(25.55,98.35) v1(25.65,67.31) v1(25.65,65.15) v1(25.65,30.35) v1(25.78,27.94) v1(25.78,25.53) v1(25.78,22.23) v1(25.91,33.78) v1(25.91,20.32) v1(25.91,17.53) v1(26.04,80.39) v1(26.11,97.49) v1(26.21,105.08) v1(26.19,103.68) v1(26.16,84.33) v1(26.29,74.68) v1(26.29,72.39) v1(26.29,68.45) v1(26.59,98.27) v1(26.8,53.47) v1(26.95,97.05) v1(27.43,57.4) v1(27.71,98.35) v1(27.81,97.43) v1(27.94,96.27) v1(28.19,50.29) v1(28.32,35.69) v1(28.32,32.13) v1(28.32,30.1) v1(28.45,54.36) v1(28.47,103.58) v1(28.63,22.11) v1(28.7,88.77) v1(28.69,83.86) v1(28.7,23.19) v1(28.75,21.19) v1(28.88,24.55) v1(29,55.97) v1(29.31,102.4) v1(29.46,103.5) v1(29.46,85.98) v1(29.72,12.06) v1(29.84,24.96) v1(29.97,97.41) v1(30.01,84.84) v1(30.23,102.87) v1(30.23,29.92) v1(30.2,29) v1(30.21,27.99) v1(30.25,37.24) v1(30.25,35.94) v1(30.3,34.92) v1(30.25,33.88) v1(30.28,32.92) v1(30.25,31.83) v1(30.28,30.91) v1(30.35,57.4) v1(30.51,27.13) v1(30.82,25.24) v1(30.82,16.06) v1(30.86,26.26) v1(30.9,20.47) v1(30.87,19.04) v1(30.86,17.58) v1(31.11,110.24) v1(31.62,106.05) v1(31.75,102.62) v1(32.13,97.28) v1(32.43,87.16) v1(32.89,57.4) v1(33.15,108.08) v1(33.15,54.74) v1(33.07,16.1) v1(33.4,99.57) v1(33.6,89.19) v1(33.78,101.85) v1(33.91,103.38) v1(33.91,12.06) v1(34.02,88.03) v1(34.14,75.02) v1(34.21,65.27) v1(34.16,53.98) v1(34.29,97.41) v1(34.29,55.88) v1(34.42,91.82) v1(34.42,34.98) v1(34.47,33.91) v1(34.49,32.84) v1(34.62,44.35) v1(34.67,110.24) v1(34.72,36.02) v1(34.8,106.17) v1(34.8,94.74) v1(34.77,31.67) v1(35.26,43.74) v1(35.27,16.13) v1(35.74,37.95) v1(35.76,42.77) v1(35.94,92.71) v1(35.86,40.69) v1(35.97,41.71) v1(36.45,108.2) v1(36.45,101.6) v1(36.58,91.69) v1(36.78,29.67) v1(37.21,54.1) v1(37.37,92.74) v1(37.52,16.11) v1(37.67,28.73) v1(37.83,68.83) v1(37.97,12.06) v1(38.1,110.24) v1(38.1,106.3) v1(38.1,99.44) v1(38.1,95) v1(38.23,97.54) v1(38.32,91.75) v1(38.51,27.91) v1(38.61,55.12) v1(39.24,44.2) v1(39.62,101.47) v1(39.59,25.86) v1(39.59,23.61) v1(39.59,21.96) v1(39.75,108.08) v1(39.75,104.39) v1(40.51,95.38) v1(40.72,86.24) v1(40.7,83.5) v1(40.75,88.5) v1(41.15,62.1) v1(41.21,91.31) v1(41.3,46.16) v1(41.4,110.24) v1(41.4,106.3) v1(41.4,99.57) v1(41.45,52.55) v1(41.61,50.27) v1(41.78,102.11) v1(41.76,20.29) v1(41.79,18.19) v1(41.79,16.47) v1(42.04,25.9) v1(42.08,64.43) v1(42.35,23.23) v1(42.29,12.06) v1(42.42,97.54) v1(42.36,45.08) v1(42.72,24.66) v1(43.05,108.08) v1(43.05,88.01) v1(43.18,54.13) v1(43.31,84.71) v1(43.31,82.3) v1(43.32,76.95) v1(43.32,74.46) v1(43.38,79.53) v1(43.41,71.97) v1(43.44,69.28) v1(43.47,43.97) v1(43.69,92.8) v1(43.69,66.53) v1(43.81,90.04) v1(44.2,30.35) v1(44.2,26.16) v1(44.2,20.83) v1(44.4,86.65) v1(44.39,42.65) v1(44.58,110.24) v1(44.7,106.17) v1(44.7,101.73) v1(44.7,99.57) v1(44.91,49.81) v1(44.92,18.05) v1(45.11,88.77) v1(45.15,45.36) v1(45.3,64.73) v1(45.37,63.01) v1(45.47,97.41) v1(45.47,37.08) v1(45.85,12.06) v1(46.1,83.57) v1(46.23,86.61) v1(46.21,52.97) v1(46.48,90.04) v1(46.61,107.95) v1(46.61,104.27) v1(47.17,44.43) v1(47.89,63.23) v1(48.13,84.84) v1(48.26,106.3) v1(48.33,50.7) v1(48.39,110.24) v1(48.39,99.57) v1(48.43,64.72) v1(48.51,101.6) v1(48.51,33.02) v1(48.51,28.07) v1(48.51,23.11) v1(48.51,12.06) v1(48.64,16.76) v1(48.74,43.08) v1(48.9,97.41) v1(49.02,19.69) v1(49.16,60.77) v1(49.28,37.72) v1(49.78,104.39) v1(49.91,81.79) v1(49.91,77.98) v1(49.91,74.04) v1(49.91,69.98) v1(49.91,66.04) v1(49.91,44.46) v1(50.28,83.7) v1(51.38,43.07) v1(51.56,40.77) v1(51.82,99.57) v1(51.94,84.84) v1(51.89,80.44) v1(51.89,77.64) v1(52.11,73.31) v1(52.11,70.77) v1(52.61,44.44) v1(52.58,30.48) v1(52.58,26.16) v1(53.59,83.19) v1(53.59,79.5) v1(53.59,75.69) v1(53.59,72.14) v1(53.59,68.45) v1(53.59,20.95) v1(53.72,64.52) v1(53.72,60.33) v1(53.72,55.75) v1(53.72,50.93) v1(53.72,46.36) v1(53.72,42.29) v1(53.72,36.96) v1(53.72,33.02) v1(53.72,28.96) v1(53.72,24.26) v1(53.72,18.16) v1(54.1,104.9) v1(54.1,102.87) v1(54.1,100.71) v1(54.1,98.55) v2(11.18,38.23)
GND_FIELD SIGNAL: length 13.7
  TOP w0.254: U1.18 19.14,48.55 v1(18.92,48.34) ; U1.17 19.12,49.06 v1(18.9,49.28)
  TOP w0.305: v1(41.25,56.74) 41.78,56.74 43.33,58.3 U6.4 ; v1(41.3,60.68) 42.34,60.68 43.22,59.8 U6.1
  TOP w0.508: L3.1 v1(13.26,48.31) ; C12.2 v1(16.18,48.29) ; C11.2 v1(14.86,48.36) ; C40.2 v1(39.75,60.2) ; C21.2 v1(39.75,57.54)
  BOTTOM w0.508: C24.1 v1(21.72,49.02)
VBATT: length 6.6
  BOTTOM w0.508: D1.1 16.08,87.97 v1(16.23,88.11) ; U3.1 16.83,88.96 v1(16.59,89.2) ; C6.1 v1(10.3,88.9) ; Q1.2 v1(9.13,87.91) ; 17.65,87.25 v1(16.9,87.25) ; U3.3 v1(16.7,90.87)
VBUS: length 94.2
  BOTTOM w0.254: U2.1 25.29,94.42 25.96,95.09 33.03,95.09 v1(34.37,93.75)
  BOTTOM w0.508: L2.1 17.98,64.2 18.43,64.64 C4.1 19.94,66.29 20.83,67.18 20.83,81.61 19.51,82.93 10.3,82.93 8.13,85.11 8.13,90.35 8.51,90.73 Q1.1 10.6,90.73 10.68,90.81 R8.1 12.18,90.81 13.24,91.87 D1.2 21.29,91.87 22.46,90.7 24.15,90.7 24.53,90.32 30.94,90.32 v1(34.37,93.75) 46.28,93.75 47.12,92.91 J1.1
VDDA: length 9.6
  TOP w0.203: U1.36 26.94,44.18 v1(26.04,45.09) ; C11.1 v1(14.86,50.88) ; C12.1 v1(16.18,50.89)
  TOP w0.305: C40.1 40.77,59.98 ; C40.1 40.77,58.89 ; C40.1 41.31,59.44 ; 42.93,59.08 43.21,58.8 U6.3 ; 40.77,57.75 C21.1 ; C21.1 41.31,58.29 ; C21.1 40.77,58.84
  BOTTOM w0.203: L4.1 27.56,85.42 28.02,84.96 v1(28.22,84.96)
  vias: v1(41.38,58.88)
VINN1: length 4.4
  TOP w0.203: U1.23 18.92,46.05 18.5,45.63 17.9,45.63 R22.1 R20.2
VINN2: length 9.5
  TOP w0.203: R21.1 R20.1 20.47,43.71 22.1,45.34 22.94,45.34 23.44,44.83 23.44,44.41 23.44,44.41 U1.29
VINP1: length 41.2
  TOP w0.203: U1.22 v1(18.29,46.55)
  BOTTOM w0.203: J9.2 J9.4 J9.6 J9.8 J9.10 J9.12 9.55,64.91 14.13,60.33 14.13,48.27 15.84,46.55 v1(18.29,46.55)
VINP2: length 97.3
  TOP w0.203: v1(22.64,44.7) 22.94,44.41 U1.28 ; v1(36.07,64.77) 36.07,58.85 32.46,55.25 v1(27.56,55.25)
  BOTTOM w0.203: J10.6 J10.5 ; J10.6 J10.4 ; J10.6 J10.8 ; J10.5 J10.7 ; J10.5 J10.3 ; v1(27.56,55.25) 25.87,53.55 25.87,51.27 24.77,50.16 24.77,46.82 v1(22.64,44.7) ; J10.4 J10.2 J10.1 ; J10.4 J10.3 ; J10.1 J10.3 ; J10.1 40.54,67.14 40.55,67.13 40.55,65.94 39.38,64.77 v1(36.07,64.77) ; J10.9 J10.11 J10.12 J10.10 ; J10.9 J10.10 ; J10.9 J10.7 ; J10.7 J10.8 ; J10.8 J10.10
ACC_INT: length 11.6
  TOP w0.203: U1.75 35.69,57.49 35.88,57.68 v1(36.66,57.68) ; v1(41.25,54.76) 41.25,55.35 41.47,55.57 41.47,55.57 43.71,57.8 U6.5
  BOTTOM w0.203: v1(36.66,57.68) 38.34,57.68 v1(41.25,54.76)
ACC_SCL: length 21.7
  TOP w0.203: v1(49.78,57.81) 49.78,57.07 47.76,55.05 46.38,55.05 42.88,51.55 39.68,51.55 39.68,51.55 39.19,51.55 39.18,51.55 U1.64 ; v1(49.78,57.81) 48.44,57.81 48.43,57.8 U6.6 ; v1(49.78,57.81) R13.2
ACC_SDA: length 26.3
  TOP w0.203: U6.7 47.89,58.3 v1(49.25,59.66) R9.2 ; v1(37.59,50.55) 37.08,51.05 U1.63
  BOTTOM w0.203: v1(49.25,59.66) 46.92,59.66 44.76,57.51 44.76,51.7 42.16,49.1 39.04,49.1 v1(37.59,50.55)
BK_LIGHT: length 7.5
  TOP w0.203: U1.87 28.44,64.19 28.24,64.39 v1(28.24,64.97)
  BOTTOM w0.203: v1(28.24,64.97) 28.27,64.97 28.57,65.28 Q4.1
BKGD: length 12.6
  TOP w0.203: U1.59 36.79,49.06 38.1,47.75 41.78,47.75 43.22,46.31 J12.1
BUZZER: length 67.7
  TOP w0.203: v1(39.52,49.76) 37.52,49.76 36.72,50.55 U1.62 ; v1(40.16,55.02) 38.94,56.23 38.94,64.36 42.02,67.44 42.02,92.41 32.74,101.69 29.81,101.69 28.7,100.58 R40.1
  BOTTOM w0.203: v1(39.52,49.76) 40.16,50.39 v1(40.16,55.02)
EXTAL1: length 6.4
  TOP w0.203: U1.38 27.94,44.32 27.65,44.62 v1(27.64,44.62)
  BOTTOM w0.203: v1(27.64,44.62) R42.1 27.64,45.9 27.54,45.99 27.54,46 26.58,46.96 Y4.2 26.57,47.23 C42.2
EXTAL2: length 7.3
  TOP w0.203: C28.2 Y3.3 28.69,38.42 29.64,39.36 29.64,41.15 R15.1 29.44,41.86 U1.41
INP1+: length 4.4
  TOP w0.203: v1(21.84,52.04) 20.2,52.04 U1.11 18.53,52.05 R35.2
  BOTTOM w0.203: R28.1 v1(21.84,52.04)
INP1-: length 11.6
  TOP w0.203: v1(21.94,47.88) 21.51,47.88 21.34,48.05 U1.19 ; v1(19.51,42.2) R27.1 18.95,40.89 18.11,40.89 R34.2
  BOTTOM w0.203: v1(19.51,42.2) 19.51,45.45 v1(21.94,47.88)
INP2+: length 16.8
  TOP w0.203: C39.2 R38.1 v1(20.52,39.18) ; U1.14 v1(18.9,50.55)
  BOTTOM w0.203: v1(20.52,39.18) 18.16,41.54 18.16,45.4 19.51,46.74 19.51,49.97 19.34,50.14 19.31,50.14 v1(18.9,50.55)
LCD_CS: length 24.9
  TOP w0.203: U1.72 36.86,55.55 38.07,56.77 38.07,65.37 v1(38.92,66.21) 36.54,68.59 36.54,75.67 36.72,75.86 DS1.8
LCD_D0: length 23.3
  TOP w0.203: DS1.12 36.86,79.05 33.32,75.52 33.32,66.04 33.03,65.75 v1(33.03,65.16) 33.03,64.58 32.94,64.5 U1.78
LCD_D1: length 24.4
  TOP w0.203: DS1.13 36.72,79.86 33.06,76.2 33.06,75.86 32.54,75.34 v1(32.54,75.01) 32.54,74.42 32.44,74.32 U1.79
LCD_D2: length 25.3
  TOP w0.203: DS1.14 36.88,80.66 32.86,76.64 32.86,76.64 v1(32.44,76.23) 31.94,75.72 U1.80
LCD_D3: length 26.3
  TOP w0.203: U1.81 31.44,76.06 v1(32.48,77.09) 32.89,77.5 32.89,77.53 36.81,81.46 DS1.15
LCD_D4: length 27.4
  TOP w0.203: DS1.16 36.76,82.26 32.89,78.39 32.89,78.37 v1(32.48,77.96) 30.94,76.42 U1.82
LCD_D5: length 28.4
  TOP w0.203: DS1.17 36.71,83.05 v1(32.48,78.82) 30.44,76.78 U1.83
LCD_D6: length 29.5
  TOP w0.203: U1.84 29.94,77.21 v1(32.47,79.74) 36.59,83.86 DS1.18
LCD_D7: length 30.6
  TOP w0.203: U1.85 29.44,77.69 v1(32.43,80.68) 36.41,84.66 DS1.19
LCD_RD: length 39
  TOP w0.203: DS1.11 36.85,78.26 34.92,76.33 34.92,66.03 35.35,65.6 35.35,58.8 33.23,56.68 27.31,56.68 24.69,54.05 U1.7
LCD_RS: length 24.6
  TOP w0.203: DS1.9 36.72,76.66 35.99,75.93 v1(35.99,66.86) 37.69,65.15 37.69,56.95 36.79,56.06 U1.73
LCD_RST: length 31.7
  TOP w0.203: U1.86 28.94,78.08 v1(32.42,81.56) 36.31,85.45 DS1.20
LCD_WR: length 25
  TOP w0.203: DS1.10 36.72,77.46 35.37,76.11 35.37,66.51 37.31,64.57 37.31,57.23 36.64,56.55 U1.74
MCU3.3V: length 17.9
  TOP w0.254: v1(33.9,60.13) 33.7,59.93 33.66,59.93 33.44,59.71 U1.77 ; U1.35 v1(26.44,41.76) ; U1.40 28.94,42.4 28.43,41.88 v1(28.42,41.88) ; U1.97 v1(23.44,57.55)
  TOP w0.508: R17.1 v1(47.47,54.36)
  BOTTOM w0.508: v1(28.42,41.88) 28.47,41.88 28.91,41.45 C16.1 ; v1(27.1,36.83) 26.54,37.39 C17.1 ; C23.1 26.42,41.74 v1(26.44,41.76) ; C14.1 23.37,57.48 v1(23.44,57.55) ; L4.2 v1(28.94,87.43) ; L5.1 v1(25.91,86.36) ; C13.1 C15.1 33.53,60.5 v1(33.9,60.13)
MCU_RESET: length 24.4
  TOP w0.203: R17.2 C25.2 50.78,53.34 50.79,53.35 SW2.1 51.82,50.95 J12.4 48.32,47.46 45.14,47.46 44.37,48.23 38.26,48.23 36.93,49.55 U1.60
OUT1: length 10.3
  TOP w0.203: R36.1 R27.2 v1(20.52,42.2) ; U1.20 21.3,47.55 21.78,47.07 v1(22.68,47.07)
  BOTTOM w0.203: v1(20.52,42.2) 20.52,44.91 v1(22.68,47.07)
PTG0: length 37.1
  TOP w0.203: U1.90 26.94,60.11 27.13,60.3 27.13,87.1 26.08,88.15 v1(26.08,91.1)
  BOTTOM w0.203: v1(26.08,91.1) 26.66,91.1 27.18,91.62 R6.2 26.58,92.58 26.19,92.97 U2.3
PTG1: length 66.1
  TOP w0.203: U1.91 26.44,57.45 25.93,56.94 22.23,56.94 12.83,66.34 v1(12.83,95.15) ; v1(26.67,94.48) v1(26.67,96.16)
  BOTTOM w0.203: U2.2 26.41,93.47 R5.2 v1(26.67,94.48) ; v1(12.83,95.15) 19.02,95.15 20.04,96.16 v1(26.67,96.16)
PTG2: length 35.6
  TOP w0.203: U1.89 27.44,59.91 27.56,60.03 27.56,91.25 26.92,91.88 v1(25.27,91.88)
  BOTTOM w0.203: v1(25.27,91.88) 25.27,92.04 25.29,92.06 U2.4
SD_CS: length 22.9
  TOP w0.203: CN1.2 41.23,32.11 44.7,35.58 44.7,41.26 39.42,46.55 U1.54
SD_INT: length 16.7
  TOP w0.203: U1.55 41.84,47.05 45.21,43.68 R12.2 45.21,42.49 46.93,40.76 CN1.9
SD_MISO: length 16.3
  TOP w0.203: CN1.7 42.51,37.61 43.79,38.88 43.79,41.05 39.28,45.55 U1.52
SD_MOSI: length 19.1
  TOP w0.203: v1(43.21,39.14) 43.21,41.09 39.24,45.05 U1.51 ; v1(41.39,33.21) CN1.3
  BOTTOM w0.203: v1(41.39,33.21) 43.21,35.03 v1(43.21,39.14)
SD_SCLK: length 18.7
  TOP w0.203: U1.53 39.35,46.05 44.2,41.2 44.2,38.38 41.23,35.41 CN1.5
T_CNTR: length 26.3
  TOP w0.203: v1(34.14,41.73) 34.14,41.73 33.9,41.73 33.44,42.2 U1.49 ; v1(37.29,20.68) 37.34,20.63 R47.2
  BOTTOM w0.203: v1(34.14,41.73) 34.14,37.33 33.3,36.48 33.3,30.77 37.29,26.78 J3.2 v1(37.29,20.68)
T_DWN: length 24.5
  TOP w0.203: U1.45 31.44,42.2 v1(31.15,41.91) ; v1(32.29,20.63) 32.26,20.6 R45.2
  BOTTOM w0.203: v1(32.29,20.63) J3.6 32.29,26.78 31.01,28.06 31.01,41.77 v1(31.15,41.91)
T_LEFT: length 24.8
  TOP w0.203: v1(31.59,41.15) 31.62,41.18 31.62,41.4 31.94,41.72 U1.46 ; R44.2 33.53,20.62 v1(33.54,20.63)
  BOTTOM w0.203: v1(33.54,20.63) J3.5 33.54,26.78 31.59,28.73 v1(31.59,41.15)
T_REF: length 24.8
  TOP w0.203: R43.2 34.8,20.62 v1(34.79,20.63) ; U1.47 32.44,41.61 32.45,41.6 v1(32.45,41.02)
  BOTTOM w0.203: v1(32.45,41.02) 32.45,29.13 34.79,26.78 J3.4 v1(34.79,20.63)
T_RIGHT: length 25.1
  TOP w0.203: v1(38.54,24.6) 39.84,24.6 R48.2 ; v1(35.04,41.87) 35.04,42.64 34.37,43.3 U1.50
  BOTTOM w0.203: J3.1 v1(38.54,24.6) 38.54,26.78 33.78,31.54 33.78,36.07 35.05,37.34 35.05,41.27 35.04,41.29 v1(35.04,41.87)
T_TOP: length 25.5
  TOP w0.203: v1(33.31,41.02) 33.31,41.61 32.94,41.98 U1.48 ; v1(36.04,20.63) 36.07,20.6 R46.2
  BOTTOM w0.203: v1(33.31,41.02) 32.84,40.56 32.84,29.98 36.04,26.78 J3.3 v1(36.04,20.63)
TRIOUT1: length 8.1
  TOP w0.203: U1.21 19.09,47.05 18.65,47.49 17.9,47.49 R22.2 17.48,47.67 17.45,47.69 R35.1
TRIOUT2: length 7.5
  TOP w0.203: U1.27 22.43,43.29 22.43,42.27 22.34,42.18 21.55,42.18 20.76,42.97 18.91,42.97 R21.2 18.49,41.61 18.26,41.38 R34.1
USBDM: length 53
  TOP w0.229: v1(24.58,70.41) 25.02,70.84 25.02,71.5 24.64,71.88 23.5,71.88 23.11,71.5 23.11,66.29 25.39,64.01 25.39,60.08 25.44,60.04 U1.93
  BOTTOM w0.229: R3.2 44.22,91.97 43.27,91.97 41.87,90.58 33.11,90.58 31.09,88.56 31.09,83.23 24.94,77.08 24.94,70.77 v1(24.58,70.41)
USBDP: length 53.7
  TOP w0.229: v1(25.71,70.41) 25.43,70.69 25.43,71.67 24.81,72.29 23.33,72.29 22.71,71.67 22.71,66.13 24.99,63.85 24.99,60.08 24.94,60.04 U1.94
  BOTTOM w0.229: R4.2 44.2,91.57 43.43,91.57 42.04,90.17 33.27,90.17 31.5,88.39 31.5,83.06 25.35,76.91 25.35,70.77 v1(25.71,70.41)
VREF1.6V: length 24.6
  TOP w0.254: U1.24 19.04,45.55 18.75,45.26 v1(18.75,44.83) ; U1.32 v1(24.94,44.66)
  TOP w0.508: v1(18.54,40.01) 18.85,40.31 R38.2 ; v1(24.41,41.4) 24.41,41.38 24.85,40.93 C38.2
  BOTTOM w0.508: C24.2 v1(23.37,49.77) ; R28.2 v1(24.61,52.04) ; v1(17.68,68.13) 15.4,68.13 J9.11 J9.9 J9.7 J9.5 J9.3 J9.1 17.51,80.77 v1(17.56,80.72)
XTAL1: length 6.4
  TOP w0.203: v1(28.65,44.65) 28.44,44.44 U1.39
  BOTTOM w0.203: C43.2 29.79,47.23 Y4.1 29.78,47.05 28.65,45.92 R42.2 v1(28.65,44.65)
XTAL2: length 5.2
  TOP w0.203: C29.2 Y3.1 30.79,40.89 30.78,40.9 30.78,41.02 R15.2 29.94,41.87 U1.42
ZIG_ATTN: length 53.2
  TOP w0.203: v1(17.65,59.21) 12.17,64.69 12.17,101.7 12.84,102.37 U5.14 ; U1.5 18.95,55.05 18.86,54.97 v1(17.65,54.97)
  BOTTOM w0.203: v1(17.65,54.97) v1(17.65,59.21)
ZIG_CS: length 47
  TOP w0.203: v1(17.18,65.84) 16.59,65.84 15.59,66.84 15.59,66.84 15.04,67.39 15.04,100 15.12,100.09 U5.19 ; U1.1 v1(20.19,57.68)
  BOTTOM w0.203: v1(20.19,57.68) 16.15,61.72 16.15,64.81 v1(17.18,65.84)
ZIG_INT: length 51.9
  TOP w0.203: v1(16.66,53.85) 16.96,53.55 U1.8 ; v1(16.71,66.72) 15.62,67.8 U5.20
  BOTTOM w0.203: v1(16.66,53.85) 16.66,57.86 15.62,58.91 15.62,65.64 v1(16.71,66.72)
ZIG_MISO: length 48.8
  TOP w0.203: U5.18 14.62,67.19 16.69,65.12 v1(17.72,65.12) ; v1(21.82,60.35) 22,60.35 22.44,59.91 U1.99
  BOTTOM w0.203: v1(21.82,60.35) 18.06,60.35 16.79,61.63 16.79,64.19 v1(17.72,65.12)
ZIG_MOSI: length 47
  TOP w0.203: U5.17 14.12,66.75 19.91,60.96 22.28,60.96 22.94,60.3 22.94,59.91 22.94,59.91 U1.98
ZIG_MRST: length 52.9
  TOP w0.203: U1.3 19.09,56.06 11.4,63.74 11.4,102.11 12.67,103.38 U5.12
ZIG_RXTXEN: length 53
  TOP w0.203: v1(18.37,55.57) 18.95,55.57 18.96,55.55 U1.4 ; U5.13 12.75,102.87 11.79,101.9 11.79,64.21 v1(18.44,57.56)
  BOTTOM w0.203: v1(18.37,55.57) 18.37,56.59 18.44,56.67 v1(18.44,57.56)
ZIG_SPCLK: length 46.3
  TOP w0.203: U1.100 21.51,58.8 13.47,66.84 U5.16
N01665: length 2.4
  BOTTOM w0.203: SW1.1 6.32,89.83 6.36,89.79 Q1.3
N02698: length 30.9
  TOP w0.203: v1(54.1,97.28) v1(54.1,85.32)
  BOTTOM w0.203: J1.S2 J1.S4 v1(54.1,85.32) ; v1(54.1,97.28) J1.S3 52.66,96.96 50.1,96.96 48.8,95.65 J1.S1 47.42,95.51 47.41,95.5 L1.1
N02810: length 3.1
  BOTTOM w0.203: J1.2 46.41,92.11 46.19,92.33 R3.1
N02910: length 5.3
  TOP w0.203: U1.92 25.93,58.81 25.93,59.94 v1(26.19,60.2)
  BOTTOM w0.203: C2.1 25.93,62.19 C1.1 25.93,60.45 v1(26.19,60.2)
N03154: length 70
  BOTTOM w0.203: TP30.1 4.57,54.1 v2(11.18,54.1) 11.18,55.62 3.66,63.14 3.66,88.33 3.2,88.79 3.2,91.4 4.12,92.33 SW1.2 SW1.3 4.8,94.84 6.48,94.84 7.09,94.23 C5.1 21.72,94.23 22,93.95 22.71,93.95 U2.8
N03295: length 1.6
  BOTTOM w0.203: R39.1 21.75,93.51 22.68,93.51 U2.7
N04574: length 3.3
  TOP w0.203: R10.2 38.95,30.99 38.97,31.01 CN1.1
N04614: length 3.2
  TOP w0.203: R11.2 37.56,38.73 37.58,38.71 CN1.8
N25309: length 53.2
  TOP w0.203: U1.58 34.03,48.55 v1(34.01,48.53)
  BOTTOM w0.203: R18.1 33.4,48.56 33.42,48.53 v1(34.01,48.53) ; v1(34.01,48.53) 34.42,48.95 34.42,51.85 29.24,57.04 29.24,69.19 28.7,69.72 23.78,69.72 22.23,71.28 22.23,83.69 R19.2 ; v1(34.01,48.53) 33.19,49.35 C45.1
N32500: length 2.3
  TOP w0.203: C38.1 C39.1 R36.2
N41665: length 4.9
  TOP w0.203: v1(19.38,105.92) C30.1 ; U5.30 18.68,103.88 v1(19.1,103.45)
  BOTTOM w0.203: v1(19.1,103.45) 19.8,104.15 19.8,105.5 v1(19.38,105.92)
N41677: length 1.7
  TOP w0.203: U5.21 16.13,99.57 C31.1
N41695: length 5.2
  TOP w0.203: U5.28 U5.29 18.27,103.38 17.83,103.38 17.63,103.58 17.63,104.68 17.83,104.87 U5.32 18.49,104.87 18.58,104.96 19.58,104.96 19.76,104.78 C32.1
N42211: length 3.7
  TOP w0.203: Z1.3 16.4,107.05 16.4,107.06 L6.1 17.85,106.61 17.13,105.89 U5.2
N42218: length 7.1
  TOP w0.203: L6.2 v1(18.66,108.07) 18.66,106.14 18.04,105.52 U5.1 ; v1(16.55,108.85) Z1.4
  BOTTOM w0.203: v1(18.66,108.07) 17.33,108.07 v1(16.55,108.85)
N42330: length 6.5
  TOP w0.203: C34.1 16.61,107.96 15.53,107.96 15.29,107.72 Z1.2 15.29,106.33 15.44,106.18 16.41,106.18 16.63,105.97 U5.3
N42476: length 8.3
  TOP w0.457: Z1.1 14.05,107.05 14.05,107.05 C35.1 C35.2 7.31,107.05 7.29,107.06 E1.1
N42716: length 9.5
  TOP w0.203: U5.26 18.63,101.87 18.95,101.55 18.95,98.55 19.33,98.17 21.18,98.17 21.49,98.48 Y1.1 21.53,99.95 C36.1
N42769: length 3.7
  TOP w0.203: C37.1 20.19,102.59 20.17,102.57 Y1.3 19.37,101.69 18.68,102.37 U5.27
N99672: length 3
  BOTTOM w0.203: R4.1 46.19,91.19 46.32,91.31 J1.3
N131191: length 1.6
  TOP w0.203: R40.2 26.42,102.09 Q3.1
N131207: length 9.4
  TOP w0.203: Q3.3 30.3,104.35 30.34,104.31 D2.2 32.9,104.31 32.98,104.39 LS1.2
N131223: length 5
  TOP w0.203: D2.1 29.16,100.41 C41.2 R41.2
N132740: length 25.3
  TOP w0.203: DS1.23 DS1.22 37,87.05 v1(32.39,82.45) 27.97,78.03 27.97,70.02 28.32,69.67 v1(28.32,69.09)
  BOTTOM w0.203: Q4.3 28.02,68.28 28.32,68.58 v1(28.32,69.09)
N151371: length 7.1
  TOP w0.203: U1.95 24.44,60.57 v1(23.9,61.11)
  BOTTOM w0.203: v1(23.9,61.11) 23.9,62.65 C3.1 22.45,62.67 22.39,62.74 L2.2
N217381: length 7.2
  TOP w0.203: J8.11 v1(53.23,8.85) ; J8.9 v1(50.74,8.85) ; J8.5 v1(45.66,8.85) ; J8.1 v1(40.58,8.85) ; J8.7 v1(48.23,8.85) ; J8.3 v1(43.12,8.85)
N217421: length 8.5
  TOP w0.203: J8.2 v1(39.37,1.68) ; J8.10 v1(49.53,1.59) ; J8.8 v1(46.99,1.67) ; J8.4 v1(41.91,1.72) ; J8.12 v1(52.07,1.65) ; J8.6 v1(44.45,1.67)
N217461: length 7
  TOP w0.203: J11.1 v1(4.98,8.85) ; J11.3 v1(7.6,8.85) ; J11.9 v1(15.1,8.85) ; J11.11 v1(17.53,8.85) ; J11.5 v1(10.07,8.85) ; J11.7 v1(12.72,8.85)
N217497: length 8.2
  TOP w0.203: J11.8 v1(11.43,1.71) ; J11.2 v1(3.81,1.7) ; J11.4 v1(6.35,1.66) ; J11.6 v1(8.89,1.75) ; J11.10 v1(13.97,1.73) ; J11.12 v1(16.51,1.72)

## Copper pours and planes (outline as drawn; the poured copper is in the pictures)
3.3V on L4_PWR_2: 1.27,11.68 1.27,101.22 10.92,101.22 10.92,110.74 54.61,110.74 54.61,11.68 ; 6 cut-outs
GND on TOP: 1.27,11.68 1.27,101.22 10.92,101.22 10.92,110.74 54.61,110.74 54.61,11.68 ; 29 cut-outs
GND on BOTTOM: 1.27,11.68 1.27,101.22 10.92,101.22 10.92,110.74 54.61,110.74 54.61,11.68 ; 5 cut-outs
GND on L2_GND_1: 1.27,11.68 1.27,101.22 10.92,101.22 10.92,110.74 54.61,110.74 54.61,11.68
GND on L5_GND_2: 54.61,11.68 1.4,11.81 1.28,101.22 10.92,101.22 10.92,110.74 54.61,110.74
GND_FIELD SIGNAL on L2_GND_1: 12.45,83.44 22.35,83.44 22.35,54.1 25.78,54.1 25.78,39.5 12.45,39.5
GND_FIELD SIGNAL on L5_GND_2: 12.83,61.39 12.83,41.53 44.7,41.53 44.7,61.39 28.7,61.39 28.7,86.61 25.27,86.61 25.27,61.39
VBATT on L3_PWR_1: 8,91.59 8,85.22 19.08,85.22 19.08,91.59
VDDA on TOP: 40.28,60.15 40.28,57.56 40.36,57.48 44.37,57.48 44.37,60.15
VDDA on L4_PWR_2: 12.83,61.39 12.83,41.53 44.7,41.53 44.7,61.39 28.7,61.39 28.7,86.61 25.27,86.61 25.27,61.39
MCU3.3V on L3_PWR_1: 1.27,11.68 1.27,101.22 10.92,101.22 10.92,110.74 54.61,110.74 54.61,11.68 ; 6 cut-outs
VREF1.6V on L3_PWR_1: 12.45,83.44 22.35,83.44 22.35,54.1 25.78,54.1 25.78,39.5 12.45,39.5

Small or netless copper shapes (teardrops, artwork), in the pictures only: 1 on TOP

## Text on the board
BOTTOM: 6 OF 12 | SECONDARY SIDE | 170-27305 REV D
Board Geometry/Soldermask Bottom: 10 OF 12 | SECONDARY SOLDERMASK
Ref Des/Silkscreen Bottom: BATTERY PADS | 12 OF 12 | SECONDARY SILKSCREEN
User.Comments: 1 OF 1 | TEST PROBE | 1/1 | 1
TOP: 1 OF 12 | PRIMARY SIDE
Board Geometry/Soldermask Top: 7 OF 12 | PRIMARY SOLDERMASK
Ref Des/Silkscreen Top: A | XMMACTIVITY | 9 OF 12 | PRIMARY SILKSCREEN
